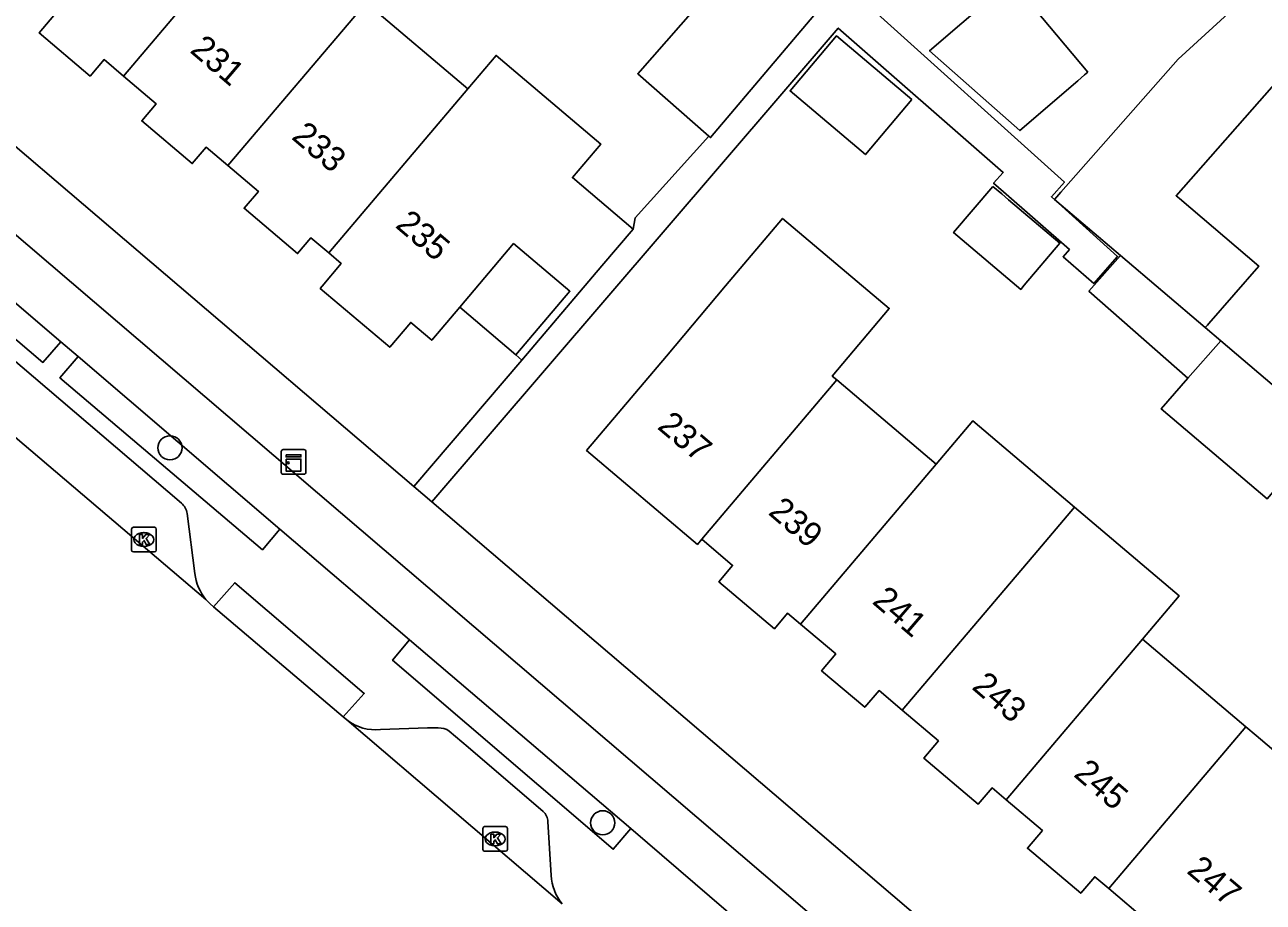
# Model space of a CAD drawing. Extents: x 162532 to 163264, y 381233 to 382042.
# Drawn here: x 162648.9 to 162699.1, y 381694.3 to 381729.9 of the extents above; entities that cross this region are included whole.
import ezdxf

# ---------------------------------------------------------------- set-up
doc = ezdxf.new("R2010")
doc.units = 0
for name, color, linetype in [('IMGEO_Berm_open', 7, 'Continuous'), ('IMGEO_Boom', 7, 'Continuous'), ('IMGEO_Fietspad_gesloten', 7, 'Continuous'), ('IMGEO_Kast', 7, 'Continuous'), ('IMGEO_Kolk', 7, 'Continuous'), ('IMGEO_Pand', 7, 'Continuous'), ('IMGEO_Pand_nummerreeks', 7, 'Continuous'), ('IMGEO_Pand_overbouw', 7, 'Continuous'), ('IMGEO_Parkeervlak_open', 7, 'Continuous'), ('IMGEO_Rijbaan_lokaal_gesloten', 7, 'Continuous'), ('IMGEO_Voetpad_open', 7, 'Continuous')]:
    doc.layers.add(name, color=color, linetype=linetype)

msp = doc.modelspace()

# ---------------------------------------------------------------- linework, layer by layer
at = {"layer": 'IMGEO_Berm_open'}
for points in [[(162642.154, 381724.027), (162641.407, 381723.174), (162649.628, 381716.181), (162650.36, 381717.013)], [(162651.057, 381716.417), (162650.32, 381715.56), (162658.523, 381708.592), (162659.232, 381709.429)], [(162664.488, 381704.937), (162663.8, 381704.114), (162672.739, 381696.454), (162673.447, 381697.303)]]:
    msp.add_lwpolyline(points, dxfattribs=at)
at = {"layer": 'IMGEO_Boom'}
for centre in [(162654.778, 381712.721), (162672.313, 381697.528)]:
    msp.add_circle(centre, 0.489, dxfattribs=at)
at = {"layer": 'IMGEO_Fietspad_gesloten'}
for points in [[(162680.601, 381693.932), (162634.563, 381733.29), (162601.096, 381761.857), (162549.056, 381806.402), (162548.287, 381807.068)], [(162642.154, 381724.027), (162650.36, 381717.013)], [(162650.36, 381717.013), (162651.057, 381716.417)], [(162651.057, 381716.417), (162659.232, 381709.429)], [(162659.232, 381709.429), (162664.488, 381704.937)], [(162664.488, 381704.937), (162673.447, 381697.303)], [(162673.447, 381697.303), (162679.253, 381692.312)]]:
    msp.add_lwpolyline(points, dxfattribs=at)
at = {"layer": 'IMGEO_Kast'}
for p, q in [((162659.289, 381711.725), (162659.289, 381712.566)), ((162659.289, 381712.566), (162659.289, 381711.725)), ((162659.364, 381712.65), (162660.205, 381712.65)), ((162660.205, 381712.65), (162659.364, 381712.65)), ((162660.289, 381712.575), (162660.289, 381711.734)), ((162660.289, 381711.734), (162660.289, 381712.575)), ((162660.214, 381711.65), (162659.373, 381711.65)), ((162659.373, 381711.65), (162660.214, 381711.65))]:
    msp.add_line(p, q, dxfattribs=at)
for points in [[(162659.484, 381712.44), (162660.084, 381712.44), (162660.084, 381712.355), (162659.484, 381712.355), (162659.484, 381712.44)], [(162659.484, 381712.265), (162660.084, 381712.265), (162660.084, 381711.776), (162659.484, 381711.776), (162659.484, 381712.265)]]:
    msp.add_lwpolyline(points, dxfattribs=at)
msp.add_circle((162659.568, 381712.114), 0.0377, dxfattribs=at)
for centre, start, end in [((162659.367, 381712.572), 92.4484, 184.2845), ((162659.367, 381712.572), 92.4484, 184.2845), ((162660.211, 381712.572), 2.4484, 94.2845), ((162660.211, 381712.572), 2.4484, 94.2845), ((162659.367, 381711.728), 182.4484, 274.2845), ((162659.367, 381711.728), 182.4484, 274.2845), ((162660.211, 381711.728), 272.4484, 4.2845), ((162660.211, 381711.728), 272.4484, 4.2845)]:
    msp.add_arc(centre, 0.0779, start, end, dxfattribs=at)
at = {"layer": 'IMGEO_Kolk'}
for p, q in [((162653.219, 381708.578), (162653.219, 381709.43)), ((162653.294, 381709.504), (162654.146, 381709.504)), ((162653.707, 381709.284), (162653.732, 381709.284)), ((162654.22, 381709.43), (162654.22, 381708.578)), ((162654.146, 381708.504), (162653.294, 381708.504)), ((162653.73, 381708.724), (162653.705, 381708.724)), ((162667.453, 381696.447), (162667.453, 381697.299)), ((162667.528, 381697.373), (162668.38, 381697.373)), ((162668.454, 381697.299), (162668.454, 381696.447)), ((162667.941, 381697.153), (162667.966, 381697.153)), ((162668.38, 381696.373), (162667.528, 381696.373)), ((162667.964, 381696.593), (162667.939, 381696.593))]:
    msp.add_line(p, q, dxfattribs=at)
for points in [[(162653.219, 381708.578), (162653.219, 381709.43)], [(162653.294, 381709.504), (162654.146, 381709.504)], [(162654.22, 381709.43), (162654.22, 381708.578)], [(162653.54, 381709.204), (162653.663, 381709.204), (162653.663, 381709.053), (162653.793, 381709.204), (162653.957, 381709.204), (162653.811, 381709.053), (162653.964, 381708.804), (162653.812, 381708.804), (162653.727, 381708.968), (162653.663, 381708.901), (162653.663, 381708.804), (162653.54, 381708.804), (162653.54, 381709.204)], [(162654.146, 381708.504), (162653.294, 381708.504)], [(162667.453, 381696.447), (162667.453, 381697.299)], [(162667.528, 381697.373), (162668.38, 381697.373)], [(162668.454, 381697.299), (162668.454, 381696.447)], [(162667.774, 381697.073), (162667.897, 381697.073), (162667.897, 381696.922), (162668.027, 381697.073), (162668.191, 381697.073), (162668.045, 381696.922), (162668.198, 381696.673), (162668.046, 381696.673), (162667.961, 381696.837), (162667.897, 381696.77), (162667.897, 381696.673), (162667.774, 381696.673), (162667.774, 381697.073)], [(162668.38, 381696.373), (162667.528, 381696.373)]]:
    msp.add_lwpolyline(points, dxfattribs=at)
for centre, start, end in [((162653.296, 381709.428), 91.552, 178.448), ((162653.296, 381709.428), 91.552, 178.448), ((162654.144, 381709.428), 1.552, 88.448), ((162654.144, 381709.428), 1.552, 88.448), ((162653.296, 381708.58), 181.552, 268.448), ((162653.296, 381708.58), 181.552, 268.448), ((162654.144, 381708.58), 271.552, 358.448), ((162654.144, 381708.58), 271.552, 358.448), ((162667.53, 381697.297), 91.552, 178.448), ((162667.53, 381697.297), 91.552, 178.448), ((162668.378, 381697.297), 1.552, 88.448), ((162668.378, 381697.297), 1.552, 88.448), ((162667.53, 381696.449), 181.552, 268.448), ((162667.53, 381696.449), 181.552, 268.448), ((162668.378, 381696.449), 271.552, 358.448), ((162668.378, 381696.449), 271.552, 358.448)]:
    msp.add_arc(centre, 0.0765, start, end, dxfattribs=at)
for centre, major_axis, ratio, start_param, end_param in [((162653.706, 381709.004), (-0.387, 0.002), 0.722429, 4.712389, 7.853982), ((162653.731, 381709.004), (-0.39, 0.002), 0.717154, 1.570796, 4.712389), ((162667.94, 381696.873), (-0.387, 0.002), 0.722429, 4.712389, 7.853982), ((162667.965, 381696.873), (-0.39, 0.002), 0.717154, 1.570796, 4.712389)]:
    msp.add_ellipse(centre, major_axis=major_axis, ratio=ratio, start_param=start_param, end_param=end_param, dxfattribs=at)
at = {"layer": 'IMGEO_Pand'}
for points in [[(162658.466, 381734.365), (162652.893, 381727.784)], [(162676.613, 381725.354), (162673.735, 381727.876), (162677.807, 381732.522)], [(162677.807, 381732.522), (162678.007, 381732.75), (162680.874, 381730.238), (162676.683, 381725.292), (162676.613, 381725.354)], [(162691.968, 381727.94), (162691.84, 381727.83), (162691.563, 381727.592), (162689.215, 381725.575), (162685.555, 381728.81), (162688.179, 381731.064), (162688.865, 381731.653), (162691.968, 381727.94)], [(162652.893, 381727.784), (162652.106, 381728.451), (162651.539, 381727.782), (162649.477, 381729.53), (162650.077, 381730.238), (162648.973, 381731.174)], [(162693.288, 381720.517), (162690.621, 381722.787), (162690.71, 381722.888), (162690.88, 381723.081), (162695.628, 381728.475), (162698.751, 381731.336)], [(162657.124, 381724.154), (162662.728, 381730.752)], [(162662.728, 381730.752), (162666.842, 381727.265)], [(162684.837, 381726.834), (162682.958, 381724.606), (162679.904, 381727.182), (162681.784, 381729.41), (162684.837, 381726.834)], [(162701.114, 381729.255), (162695.549, 381722.933), (162695.679, 381722.822), (162698.897, 381720.083), (162696.871, 381717.761), (162696.813, 381717.694), (162696.725, 381717.592)], [(162666.842, 381727.265), (162667.992, 381728.623), (162672.235, 381725.026), (162671.085, 381723.668), (162673.542, 381721.585)], [(162657.124, 381724.154), (162656.241, 381724.903), (162655.678, 381724.239), (162653.637, 381725.969), (162654.221, 381726.658), (162652.893, 381727.784)], [(162666.842, 381727.265), (162661.214, 381720.619)], [(162661.214, 381720.619), (162660.491, 381721.232), (162659.946, 381720.59), (162657.781, 381722.425), (162658.359, 381723.107), (162657.124, 381724.154)], [(162688.115, 381723.316), (162688.482, 381723.006), (162688.758, 381722.773), (162690.838, 381721.019), (162689.394, 381719.307), (162689.254, 381719.142), (162686.531, 381721.44), (162688.115, 381723.316)], [(162676.325, 381709.015), (162676.15, 381708.81), (162671.662, 381712.615), (162674.895, 381716.429), (162677.294, 381719.288), (162679.598, 381722.017), (162683.924, 381718.367), (162681.612, 381715.628), (162681.799, 381715.47)], [(162673.542, 381721.585), (162672.276, 381720.091), (162669.042, 381716.277)], [(162669.042, 381716.277), (162668.798, 381716.484), (162670.984, 381719.063), (162668.704, 381720.996), (162666.518, 381718.418), (162665.386, 381717.083), (162664.536, 381717.804), (162663.681, 381716.796), (162660.867, 381719.181), (162660.94, 381719.267), (162661.721, 381720.189), (162661.214, 381720.619)], [(162696.028, 381715.539), (162692.014, 381719.073), (162693.288, 381720.517)], [(162696.725, 381717.592), (162693.288, 381720.517)], [(162696.725, 381717.592), (162697.353, 381717.058)], [(162697.353, 381717.058), (162701.609, 381713.435), (162699.237, 381710.649), (162694.947, 381714.3), (162696.028, 381715.539)], [(162696.028, 381715.539), (162697.353, 381717.058)], [(162676.325, 381709.015), (162681.799, 381715.47)], [(162681.799, 381715.47), (162685.823, 381712.058)], [(162685.823, 381712.058), (162687.313, 381713.816), (162691.434, 381710.323)], [(162680.326, 381705.581), (162685.823, 381712.058)], [(162691.434, 381710.323), (162689.944, 381708.565), (162684.452, 381702.091)], [(162691.434, 381710.323), (162695.671, 381706.731), (162694.181, 381704.973)], [(162680.326, 381705.581), (162679.804, 381706.024), (162679.269, 381705.393), (162677.022, 381707.298), (162677.577, 381707.954), (162676.325, 381709.015)], [(162684.452, 381702.091), (162683.511, 381702.888), (162682.934, 381702.207), (162681.183, 381703.691), (162681.757, 381704.368), (162680.326, 381705.581)], [(162688.659, 381698.46), (162694.181, 381704.973)], [(162694.181, 381704.973), (162698.376, 381701.417)], [(162688.659, 381698.46), (162688.088, 381698.944), (162687.526, 381698.281), (162685.323, 381700.148), (162685.917, 381700.848), (162684.452, 381702.091)], [(162698.376, 381701.417), (162698.796, 381701.061), (162702.61, 381697.828), (162702.957, 381698.237), (162704.87, 381696.597), (162701.431, 381692.595), (162700.374, 381693.491), (162697.297, 381689.862), (162693.786, 381692.839), (162694.381, 381693.541), (162692.822, 381694.863)], [(162698.376, 381701.417), (162692.822, 381694.863)], [(162692.822, 381694.863), (162692.252, 381695.346), (162691.68, 381694.672), (162689.523, 381696.5), (162690.128, 381697.214), (162688.659, 381698.46)]]:
    msp.add_lwpolyline(points, dxfattribs=at)
at = {"layer": 'IMGEO_Pand_overbouw'}
msp.add_lwpolyline([(162666.518, 381718.418), (162668.798, 381716.484), (162670.984, 381719.063), (162668.704, 381720.996)], close=True, dxfattribs=at)
at = {"layer": 'IMGEO_Parkeervlak_open'}
for points in [[(162655.245, 381710.474), (162634.653, 381728.033)], [(162655.786, 381707.63), (162655.474, 381710.061)], [(162665.646, 381701.375), (162665.214, 381701.371), (162663.306, 381701.307)], [(162669.895, 381697.988), (162666.854, 381700.598), (162666.097, 381701.245)], [(162670.23, 381695.4), (162670.094, 381697.578)]]:
    msp.add_lwpolyline(points, dxfattribs=at)
for centre, radius, start, end in [((162654.768, 381709.94), 0.716, 9.7495, 48.2654), ((162657.804, 381707.863), 2.031, 186.577, 219.5198), ((162663.101, 381703.175), 1.879, 231.9078, 276.2569), ((162665.659, 381700.574), 0.801, 56.8916, 90.9493), ((162669.517, 381697.551), 0.577, 2.6396, 49.1411), ((162672.068, 381695.447), 1.839, 181.4704, 220.7377)]:
    msp.add_arc(centre, radius, start, end, dxfattribs=at)
at = {"layer": 'IMGEO_Rijbaan_lokaal_gesloten'}
for points in [[(162656.237, 381706.57), (162630.679, 381728.324)], [(162656.542, 381706.274), (162656.4, 381706.395), (162656.237, 381706.57)], [(162661.793, 381701.823), (162656.542, 381706.274)], [(162661.942, 381701.696), (162661.793, 381701.823)], [(162670.675, 381694.247), (162661.942, 381701.696)]]:
    msp.add_lwpolyline(points, dxfattribs=at)
at = {"layer": 'IMGEO_Voetpad_open'}
for points in [[(162634.463, 381736.935), (162664.663, 381711.149)], [(162682.334, 381731.25), (162683.048, 381730.665), (162691.024, 381723.483), (162690.494, 381722.894), (162693.179, 381720.477), (162692.208, 381719.374), (162690.968, 381720.462), (162691.224, 381720.754), (162688.556, 381723.091), (162688.153, 381723.444), (162688.541, 381723.874), (162681.858, 381729.731), (162665.388, 381710.53)], [(162673.542, 381721.585), (162673.634, 381722.046), (162676.613, 381725.354)], [(162664.663, 381711.149), (162669.042, 381716.277)], [(162664.663, 381711.149), (162665.388, 381710.53)], [(162665.388, 381710.53), (162693.781, 381686.286)], [(162661.793, 381701.823), (162662.65, 381702.77), (162657.403, 381707.255), (162656.542, 381706.274)]]:
    msp.add_lwpolyline(points, dxfattribs=at)

# ---------------------------------------------------------------- texts
at = {"layer": 'IMGEO_Pand_nummerreeks'}
for s, rotation, p in [('231', 319.5808, (162655.545, 381728.775)), ('233', 319.5808, (162659.664, 381725.267)), ('235', 319.5836, (162663.869, 381721.685)), ('237', 319.7096, (162674.484, 381713.526)), ('239', 319.3745, (162678.98, 381710.057)), ('241', 319.3745, (162683.191, 381706.445)), ('243', 319.3773, (162687.23, 381702.981)), ('245', 319.3745, (162691.354, 381699.442)), ('247', 319.7082, (162695.936, 381695.526))]:
    msp.add_text(s, height=1, rotation=rotation, dxfattribs=at).set_placement(p)

doc.saveas('drawing.dxf')
